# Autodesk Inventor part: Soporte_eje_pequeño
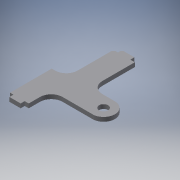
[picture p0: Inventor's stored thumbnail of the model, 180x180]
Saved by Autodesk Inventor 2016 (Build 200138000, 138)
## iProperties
Created: 2017-06
Part Number: Soporte_eje_pequeño
Material: Generic
Document SubType Name: Modeling
Designer: laboratorioesan
Density: 1 g/cm^3
Appearance: Default
Author: laboratorioesan
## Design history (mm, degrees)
sketch "Sketch1"
  geometry: L1 (0, 0)-(-50, 0) reference; L2 (0, 0)-(0, 18.5) reference; L3 (-50, 18.5)-(0, 18.5) reference; L4 (-50, 0)-(-50, 18.5) reference; L5 (75, 412.5)-(20, 412.5) reference; L6 (75, 412.5)-(75, 431) reference; L7 (20, 431)-(75, 431) reference; L8 (20, 412.5)-(20, 431) reference; L9 (75, 412.5)-(20, 412.5); L10 (20, 412.5)-(20, 430.5); L11 (20, 430.5)-(75, 430.5); L12 (75, 430.5)-(75, 412.5); L13 (-40.1, 268.5)-(200.774, 167.998); L14 (95, 872.5)-(95, 382.5) reference; L15 (75, 412.5)-(95, 412.5); L16 (95, 412.5)-(95, 217.998); L17 (95, 217.998)-(200.774, 217.998); L18 (207.839, 118.5)-(18, 118.5); L19 (0, 18.5)-(-50, 18.5); L20 (-50, 18.5)-(-50, 0.5); L21 (-50, 0.5)-(0, 0.5); L22 (0, 0.5)-(0, 18.5); L23 (0, 18.5)-(18, 18.5); L24 (18, 18.5)-(18, 118.5); L25 (20, 412.5)-(0, 412.5); L26 (0, 412.5)-(0, 203.465); L27 (0, 203.465)-(-65, 203.465); L28 (-65, 203.465)-(-65, 18.5); L29 (-65, 18.5)-(-50, 18.5); L30 (237.066, 118.5)-(-65, 118.5) reference; C1 r 24.9 at (-40.1, 268.5) reference; C2 r 20 at (200.774, 167.998); A1 r 50 centre (200.774, 167.998) between (207.839, 118.5) and (200.774, 217.998)
  constraints: 40 end point, 7 perpendicular, 6 horizontal, 4 parallel, 3 point on line, 2 centre point, 2 coincident, 2 point on circle, 1 horizontal alignment, 1 tangent, 1 vertical
  dimensions: "d0" = 18 distance of L9.end L10.end; "d1" = 261 distance of L13.start L13.end; "d2" = 40 diameter of C2; "d3" = 20 distance of L5.start L15.end; "d4" = 100 diameter of A1; "d5" = 18 distance of L20.end L19.end; "d6" = 18 distance of L2.end L23.end; "d7" = 20 distance of L9.end L25.end
extrude "Extrusion1" new body sketch "Sketch1" distance "d8" = 18.5; taper "d9" = 0 deg
fillet "Fillet1" dims "d10" = 50
body "Solid1"
node "Reference1"
node "Reference2"
node "Reference3"
node "Reference4"
node "Reference5"
